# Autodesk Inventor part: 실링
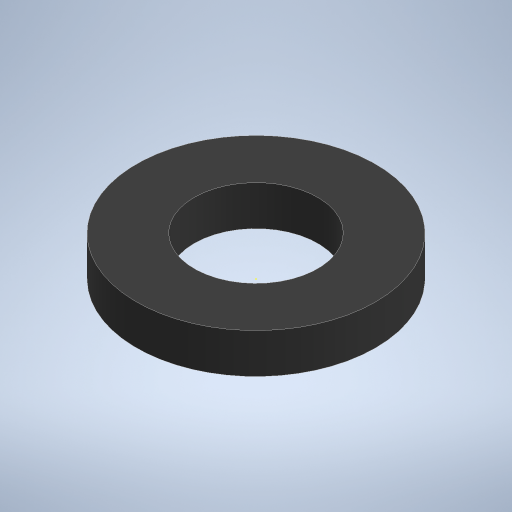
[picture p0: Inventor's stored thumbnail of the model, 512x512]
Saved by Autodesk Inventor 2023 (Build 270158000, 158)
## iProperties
Created: 2025-10
Part Number: 실링
Material: 고무
Document SubType Name: Modeling
Designer: home
Density: 0.93 g/cm^3
Appearance: 기본값
Author: jhkim
Sending System: Autodesk Inventor 2026
Preprocessor: ST-DEVELOPER v20.1
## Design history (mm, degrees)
sketch "스케치1"
  geometry: 1 further point
  constraints: 1 other
feature "솔리드1"
node "솔리드2"
